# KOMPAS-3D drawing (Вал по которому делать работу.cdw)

Views: Выносной элемент, Вид 2, Вид 3, Вид 4, Выносной элемент И
Referenced files in C:\Users\Polly\AppData\Local\Temp\: kfqlybda.cd
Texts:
  Вал
  kolly
  Обозначение узла
  Ra0.8
  D-6x26x32js6x6f8
  2. * Размер обеспечивается инструментом
  3. ГОСТ 30893.1-т
  Ra0.4
  Ra 1,6
  Ra 3,2
  Отв. центр. A4 ГОСТ 14034-74
  R0,3max
  Ra3.2
  Ra6.3
  R 0,4max
  Ra12.5
  Ra12.5 ( )
  gliv
Dimensions and other numbers on the sheet: 35; 42; 38; 30; 1,6; 3 фаски; 304; 238; 34; 45; 0.01; 1. 260...285 HB; 165; 0,010; 0,006; 0,004; 0,012; 0.008; 8; 0,002; 0,003; 2 отв.; 0,3; 3; 0.5; 1; 0,25; 32; 23,4min; 0,4; 5; 10; 1:1; 2,09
